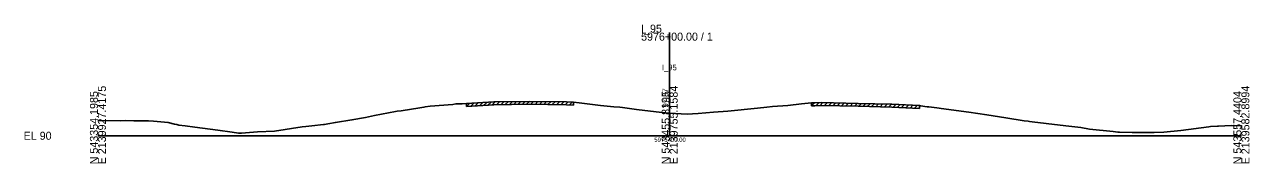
# Model space of a CAD drawing. Extents: x -12534 to 3403, y -1332 to 21983.
# Drawn here: x -25.7 to 402.8, y 10990.3 to 11038.9 of the extents above; entities that cross this region are included whole.
import ezdxf

# ---------------------------------------------------------------- set-up
doc = ezdxf.new("R2010")
doc.units = 0
for name, color, linetype in [('RD_GPK_XS_Cell', 7, 'Continuous'), ('RD_XS_ExGround', 7, 'Continuous'), ('RD_XS_ExPaveRet', 7, 'Continuous'), ('RD_XS_TX_Baseline', 7, 'Continuous'), ('RD_XS_TX_Elev_EX', 7, 'Continuous'), ('RD_XS_TX_Station', 7, 'Continuous')]:
    doc.layers.add(name, color=color, linetype=linetype)

msp = doc.modelspace()

# ---------------------------------------------------------------- linework, layer by layer
at = {"layer": 'RD_GPK_XS_Cell'}
for p, q in [((200, 11000), (200, 11036.04)), ((0, 11000), (200, 11000)), ((200, 11000), (400, 11000))]:
    msp.add_line(p, q, dxfattribs=at)
at = {"layer": 'RD_XS_ExGround'}
msp.add_lwpolyline([(0, 11005.33), (7.95, 11005.25), (9.48, 11005.28), (12.58, 11005.24), (17.68, 11005.2), (19.41, 11005.15), (24.55, 11004.58), (26.82, 11004.06), (27.62, 11003.89), (28.27, 11003.67), (30.55, 11003.42), (33.9, 11002.99), (41.92, 11001.95), (46.99, 11001.23), (49.15, 11000.96), (49.88, 11000.91), (50.2, 11000.86), (55.81, 11001.35), (61.8, 11001.6), (71.49, 11003.06), (72.68, 11003.24), (74.86, 11003.51), (78.92, 11003.95), (79.31, 11003.99), (80.44, 11004.18), (83.05, 11004.64), (88.83, 11005.55), (93.63, 11006.4), (96.7, 11007.03), (104.14, 11008.45), (104.63, 11008.54), (106.02, 11008.74), (112.56, 11009.75), (114.03, 11009.97), (114.47, 11010.09), (116.18, 11010.31), (124.13, 11010.96), (125.25, 11011.12), (127.38, 11011.19), (128.93, 11011.22), (138.54, 11011.81), (150.9, 11012.01), (163.92, 11011.8), (166.37, 11011.71), (168.33, 11011.46), (175.77, 11010.57), (178.13, 11010.32), (180.42, 11010.11), (182.51, 11009.94), (183.48, 11009.82), (188.45, 11009.19), (199.3, 11007.91), (200, 11007.87), (206.14, 11007.53), (208.04, 11007.66), (210.02, 11007.83), (215.33, 11008.27), (220.3, 11008.61), (230.68, 11009.7), (233.95, 11010.04), (235.96, 11010.22), (241.33, 11010.63), (246.14, 11011.12), (249.63, 11011.47), (250.74, 11011.46), (253.03, 11011.61), (265.93, 11011.3), (277.74, 11011.03), (287.36, 11010.54), (287.79, 11010.46), (290.05, 11010.16), (290.71, 11010.07), (293.41, 11009.77), (294.31, 11009.67), (294.97, 11009.58), (304.64, 11008.24), (311, 11007.27), (315.43, 11006.62), (317.63, 11006.26), (324.04, 11005.27), (325.42, 11005.07), (325.88, 11005), (326.86, 11004.88), (336.59, 11003.71), (339.62, 11003.37), (343.78, 11002.84), (346.9, 11002.34), (355.19, 11001.44), (356.82, 11001.28), (357.34, 11001.24), (361.79, 11001.19), (364.83, 11001.15), (369.52, 11001.09), (372.85, 11001.28), (378.84, 11001.86), (388.57, 11003.11), (389.21, 11003.21), (391.7, 11003.37), (392.05, 11003.37), (396.42, 11003.63), (400, 11003.49)], dxfattribs=at)
at = {"layer": 'RD_XS_ExPaveRet'}
for p, q in [((128.93, 11010.22), (130, 11011.29)), ((128.93, 11010.22), (128.93, 11011.22)), ((128.93, 11010.22), (138.54, 11010.81)), ((130.43, 11010.31), (131.5, 11011.38)), ((131.93, 11010.4), (133, 11011.47)), ((133.43, 11010.5), (134.5, 11011.56)), ((134.93, 11010.59), (136, 11011.65)), ((136.43, 11010.68), (137.5, 11011.75)), ((137.93, 11010.77), (138.98, 11011.82)), ((138.54, 11010.81), (150.9, 11011.01)), ((139.43, 11010.82), (140.45, 11011.84)), ((140.93, 11010.85), (141.95, 11011.87)), ((142.43, 11010.87), (143.45, 11011.89)), ((143.93, 11010.9), (144.95, 11011.91)), ((145.43, 11010.92), (146.45, 11011.94)), ((146.93, 11010.95), (147.95, 11011.96)), ((148.43, 11010.97), (149.45, 11011.99)), ((149.93, 11011), (150.95, 11012.01)), ((150.9, 11011.01), (163.92, 11010.8)), ((151.43, 11011), (152.42, 11011.99)), ((152.93, 11010.98), (153.92, 11011.96)), ((154.43, 11010.96), (155.42, 11011.94)), ((155.93, 11010.93), (156.92, 11011.92)), ((157.43, 11010.91), (158.42, 11011.89)), ((158.93, 11010.88), (159.92, 11011.87)), ((160.43, 11010.86), (161.42, 11011.84)), ((161.93, 11010.84), (162.92, 11011.82)), ((163.43, 11010.81), (164.41, 11011.79)), ((163.92, 11010.8), (166.37, 11010.71)), ((164.93, 11010.77), (165.9, 11011.73)), ((166.37, 11011.71), (166.37, 11010.71)), ((249.63, 11010.47), (249.63, 11011.47)), ((249.63, 11010.47), (250.62, 11011.46)), ((249.63, 11010.47), (250.74, 11010.46)), ((250.74, 11010.46), (253.03, 11010.61)), ((251.13, 11010.48), (252.2, 11011.55)), ((252.63, 11010.58), (253.64, 11011.6)), ((253.03, 11010.61), (265.93, 11010.3)), ((254.13, 11010.58), (255.1, 11011.56)), ((255.63, 11010.55), (256.6, 11011.52)), ((257.13, 11010.51), (258.1, 11011.49)), ((258.63, 11010.47), (259.6, 11011.45)), ((260.13, 11010.44), (261.1, 11011.41)), ((261.63, 11010.4), (262.6, 11011.38)), ((263.13, 11010.37), (264.1, 11011.34)), ((264.63, 11010.33), (265.6, 11011.31)), ((265.93, 11010.3), (277.74, 11010.03)), ((266.13, 11010.29), (267.11, 11011.27)), ((267.63, 11010.26), (268.61, 11011.24)), ((269.13, 11010.22), (270.11, 11011.2)), ((270.63, 11010.19), (271.61, 11011.17)), ((272.13, 11010.16), (273.11, 11011.13)), ((273.63, 11010.12), (274.61, 11011.1)), ((275.13, 11010.09), (276.11, 11011.07)), ((276.63, 11010.05), (277.61, 11011.03)), ((277.74, 11010.03), (287.36, 11009.54)), ((278.13, 11010.01), (279.08, 11010.96)), ((279.63, 11009.93), (280.58, 11010.88)), ((281.13, 11009.86), (282.08, 11010.81)), ((282.63, 11009.78), (283.58, 11010.73)), ((284.13, 11009.7), (285.08, 11010.66)), ((285.63, 11009.63), (286.58, 11010.58)), ((287.36, 11010.54), (287.36, 11009.54))]:
    msp.add_line(p, q, dxfattribs=at)

# ---------------------------------------------------------------- texts
at = {"layer": 'RD_GPK_XS_Cell'}
for s, p in [('5976+00.00 / 1', (190, 11033.24)), ('I_95', (190, 11036.04)), ('EL 90', (-26, 10998.6))]:
    msp.add_text(s, height=2.8, dxfattribs=at).set_placement(p)
for s, p in [('N 543354.1985', (0, 10990)), ('E 2139927.4175', (2.8, 10990)), ('N 543455.8195', (200, 10990)), ('E 2139755.1584', (202.8, 10990)), ('N 543557.4404', (400, 10990)), ('E 2139582.8994', (402.8, 10990))]:
    msp.add_text(s, height=2.8, rotation=90, dxfattribs=at).set_placement(p)
at = {"layer": 'RD_XS_TX_Baseline'}
msp.add_text('I_95', height=2, dxfattribs=at).set_placement((197.28, 11022.87))
at = {"layer": 'RD_XS_TX_Elev_EX'}
msp.add_text('97.87', height=2, rotation=90, dxfattribs=at).set_placement((199.5, 11009.87))
at = {"layer": 'RD_XS_TX_Station'}
msp.add_text('5976+00.00', height=1.5, dxfattribs=at).set_placement((194.62, 10997.87))

doc.saveas('drawing.dxf')
